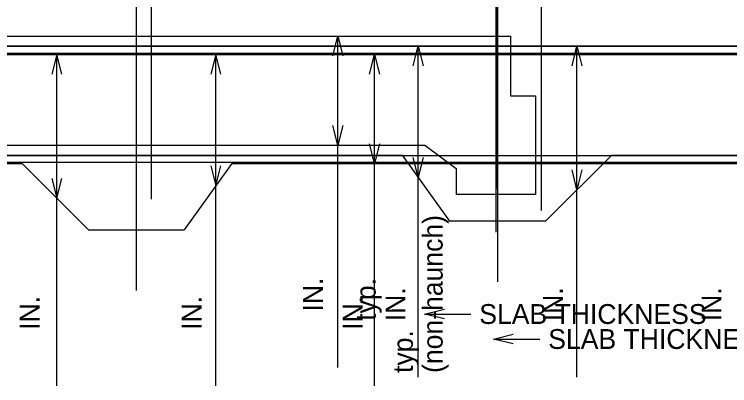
# Model space of a CAD drawing. Extents: x -6.7 to 29.5, y -5.1 to 20.6.
# Drawn here: x 4.22 to 8.723, y 12.449 to 14.787 of the extents above; entities that cross this region are included whole.
import ezdxf

# ---------------------------------------------------------------- set-up
doc = ezdxf.new("R2010")
doc.units = 0
for name, color, linetype in [('Level 5', 7, 'Continuous'), ('Level 6', 7, 'Continuous'), ('Level 7', 7, 'Continuous'), ('Level 8', 7, 'Continuous'), ('Level 9', 7, 'Continuous')]:
    doc.layers.add(name, color=color, linetype=linetype)

msp = doc.modelspace()

# ---------------------------------------------------------------- linework, layer by layer
at = {"layer": 'Level 5'}
for p, q in [((7.2506, 15.9648), (7.2506, 13.4142)), ((7.2511, 15.9707), (7.2511, 13.6584)), ((7.2564, 15.9707), (7.2564, 13.6874)), ((2.1636, 14.6495), (7.3436, 14.6495)), ((6.2564, 13.8595), (6.2564, 14.6495)), ((6.3189, 14.6495), (6.3189, 14.6495)), ((7.3436, 14.6495), (7.3436, 14.2745)), ((7.3436, 14.2745), (7.5006, 14.2745)), ((7.5006, 14.2745), (7.5006, 13.6518)), ((2.704, 13.962), (6.8033, 13.962)), ((6.8033, 13.962), (7.0006, 13.8154)), ((6.2564, 12.5639), (6.2564, 13.8595)), ((7.0006, 13.8154), (7.0006, 13.6518)), ((7.5006, 13.6518), (7.0006, 13.6518)), ((6.8021, 12.8998), (7.0943, 12.8998))]:
    msp.add_line(p, q, dxfattribs=at)
for points in [[(6.2252, 14.5245), (6.2564, 14.6495), (6.2877, 14.5245)], [(6.2877, 14.087), (6.2564, 13.962), (6.2252, 14.087)], [(6.9271, 12.8686), (6.8021, 12.8998), (6.9271, 12.9311)]]:
    msp.add_lwpolyline(points, dxfattribs=at)
at = {"layer": 'Level 6'}
for p, q in [((5.081, 15.9069), (5.081, 13.6236)), ((-0.0118, 14.5857), (10.1735, 14.5857)), ((0.5286, 13.8982), (5.081, 13.8982)), ((5.081, 13.8982), (9.6332, 13.8982))]:
    msp.add_line(p, q, dxfattribs=at)
at = {"layer": 'Level 7'}
for p, q in [((7.5372, 15.8636), (7.5372, 13.5513)), ((-2.5556, 14.5424), (12.6301, 14.5424)), ((2.5372, 13.8549), (7.5372, 13.8549)), ((7.5372, 13.8549), (12.0897, 13.8549))]:
    msp.add_line(p, q, dxfattribs=at)
at = {"layer": 'Level 8'}
for p, q in [((4.9882, 15.8553), (4.9882, 13.0488)), ((-0.1047, 14.5341), (10.0808, 14.5341)), ((4.4257, 14.5341), (4.4257, 14.5341)), ((4.4882, 13.409), (4.4882, 14.5341)), ((4.5507, 14.5341), (4.5507, 14.5341)), ((5.4257, 14.5341), (5.4257, 14.5341)), ((5.4882, 13.54), (5.4882, 14.5341)), ((5.5507, 14.5341), (5.5507, 14.5341)), ((6.4882, 13.8466), (6.4882, 14.5341)), ((6.5507, 14.5341), (6.5507, 14.5341)), ((0.4357, 13.8466), (4.2688, 13.8466)), ((4.2688, 13.8466), (4.6868, 13.4309)), ((5.5887, 13.8466), (5.2895, 13.4309)), ((5.5887, 13.8466), (9.5404, 13.8466)), ((6.4882, 12.4485), (6.4882, 13.8466)), ((6.5507, 13.8466), (6.5507, 13.8466)), ((5.4882, 12.4485), (5.4882, 13.54)), ((4.6868, 13.4309), (5.2895, 13.4309)), ((4.4882, 12.4485), (4.4882, 13.409)), ((7.2361, 12.7425), (7.5283, 12.7425))]:
    msp.add_line(p, q, dxfattribs=at)
for points in [[(4.5194, 14.4091), (4.4882, 14.5341), (4.4569, 14.4091)], [(5.5194, 14.4091), (5.4882, 14.5341), (5.4569, 14.4091)], [(6.4569, 14.4091), (6.4882, 14.5341), (6.5194, 14.4091)], [(6.5194, 13.9716), (6.4882, 13.8466), (6.4569, 13.9716)], [(5.4569, 13.8319), (5.4882, 13.7069), (5.5194, 13.8319)], [(4.4569, 13.7534), (4.4882, 13.6284), (4.5194, 13.7534)], [(7.3611, 12.7113), (7.2361, 12.7425), (7.3611, 12.7738)]]:
    msp.add_lwpolyline(points, dxfattribs=at)
at = {"layer": 'Level 9'}
for p, q in [((7.2619, 15.9094), (7.2619, 13.1029)), ((-2.831, 14.5882), (12.3547, 14.5882)), ((6.7619, 13.5942), (6.7619, 14.5882)), ((6.8244, 14.5882), (6.8244, 14.5882)), ((7.7619, 13.4631), (7.7619, 14.5882)), ((7.8244, 14.5882), (7.8244, 14.5882)), ((2.8624, 13.9007), (6.6614, 13.9007)), ((6.6614, 13.9007), (6.9605, 13.485)), ((7.9812, 13.9007), (7.5632, 13.485)), ((7.9812, 13.9007), (11.8144, 13.9007)), ((6.7619, 12.5026), (6.7619, 13.5942)), ((7.5632, 13.485), (6.9605, 13.485)), ((7.7619, 12.5026), (7.7619, 13.4631))]:
    msp.add_line(p, q, dxfattribs=at)
for points in [[(6.7306, 14.4632), (6.7619, 14.5882), (6.7931, 14.4632)], [(7.7306, 14.4632), (7.7619, 14.5882), (7.7931, 14.4632)], [(6.7931, 13.886), (6.7619, 13.761), (6.7306, 13.886)], [(7.7931, 13.8075), (7.7619, 13.6825), (7.7306, 13.8075)]]:
    msp.add_lwpolyline(points, dxfattribs=at)

# ---------------------------------------------------------------- texts
at = {"layer": 'Level 5'}
for s, p in [('     IN.', (6.1628, 12.6834)), ('typ.', (6.4952, 12.8572))]:
    msp.add_text(s, height=0.125, rotation=90, dxfattribs=at).set_placement(p)
msp.add_text('SLAB THICKNESS', height=0.125, dxfattribs=at).set_placement((7.147, 12.8373))
at = {"layer": 'Level 8'}
for s, p in [('(non-haunch)', (6.9164, 12.5287)), ('     IN.', (4.379, 12.568)), ('     IN.', (5.3994, 12.568)), ('     IN.', (6.4125, 12.568)), ('typ.', (6.7289, 12.5287))]:
    msp.add_text(s, height=0.125, rotation=90, dxfattribs=at).set_placement(p)
msp.add_text('SLAB THICKNESS', height=0.125, dxfattribs=at).set_placement((7.581, 12.68))
at = {"layer": 'Level 9'}
for p in [(6.6817, 12.6221), (7.673, 12.6221), (8.6715, 12.6221)]:
    msp.add_text('     IN.', height=0.125, rotation=90, dxfattribs=at).set_placement(p)

doc.saveas('drawing.dxf')
